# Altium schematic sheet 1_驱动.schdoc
size 604 x 431 mm; Symbol: Sheet-Symbol_A2; Device: Sheet-Symbol_A2; Company: 嘉立创EDA; Version: V1.0; Page Size: A2; @Project Name: 辉光管时钟成品; @Page Count: 1; @Update Date: 2024-01-29; @Create Date: 2024-01-25; @Schematic Name: Schematic1; @Page No: 1; @Page Name: 驱动
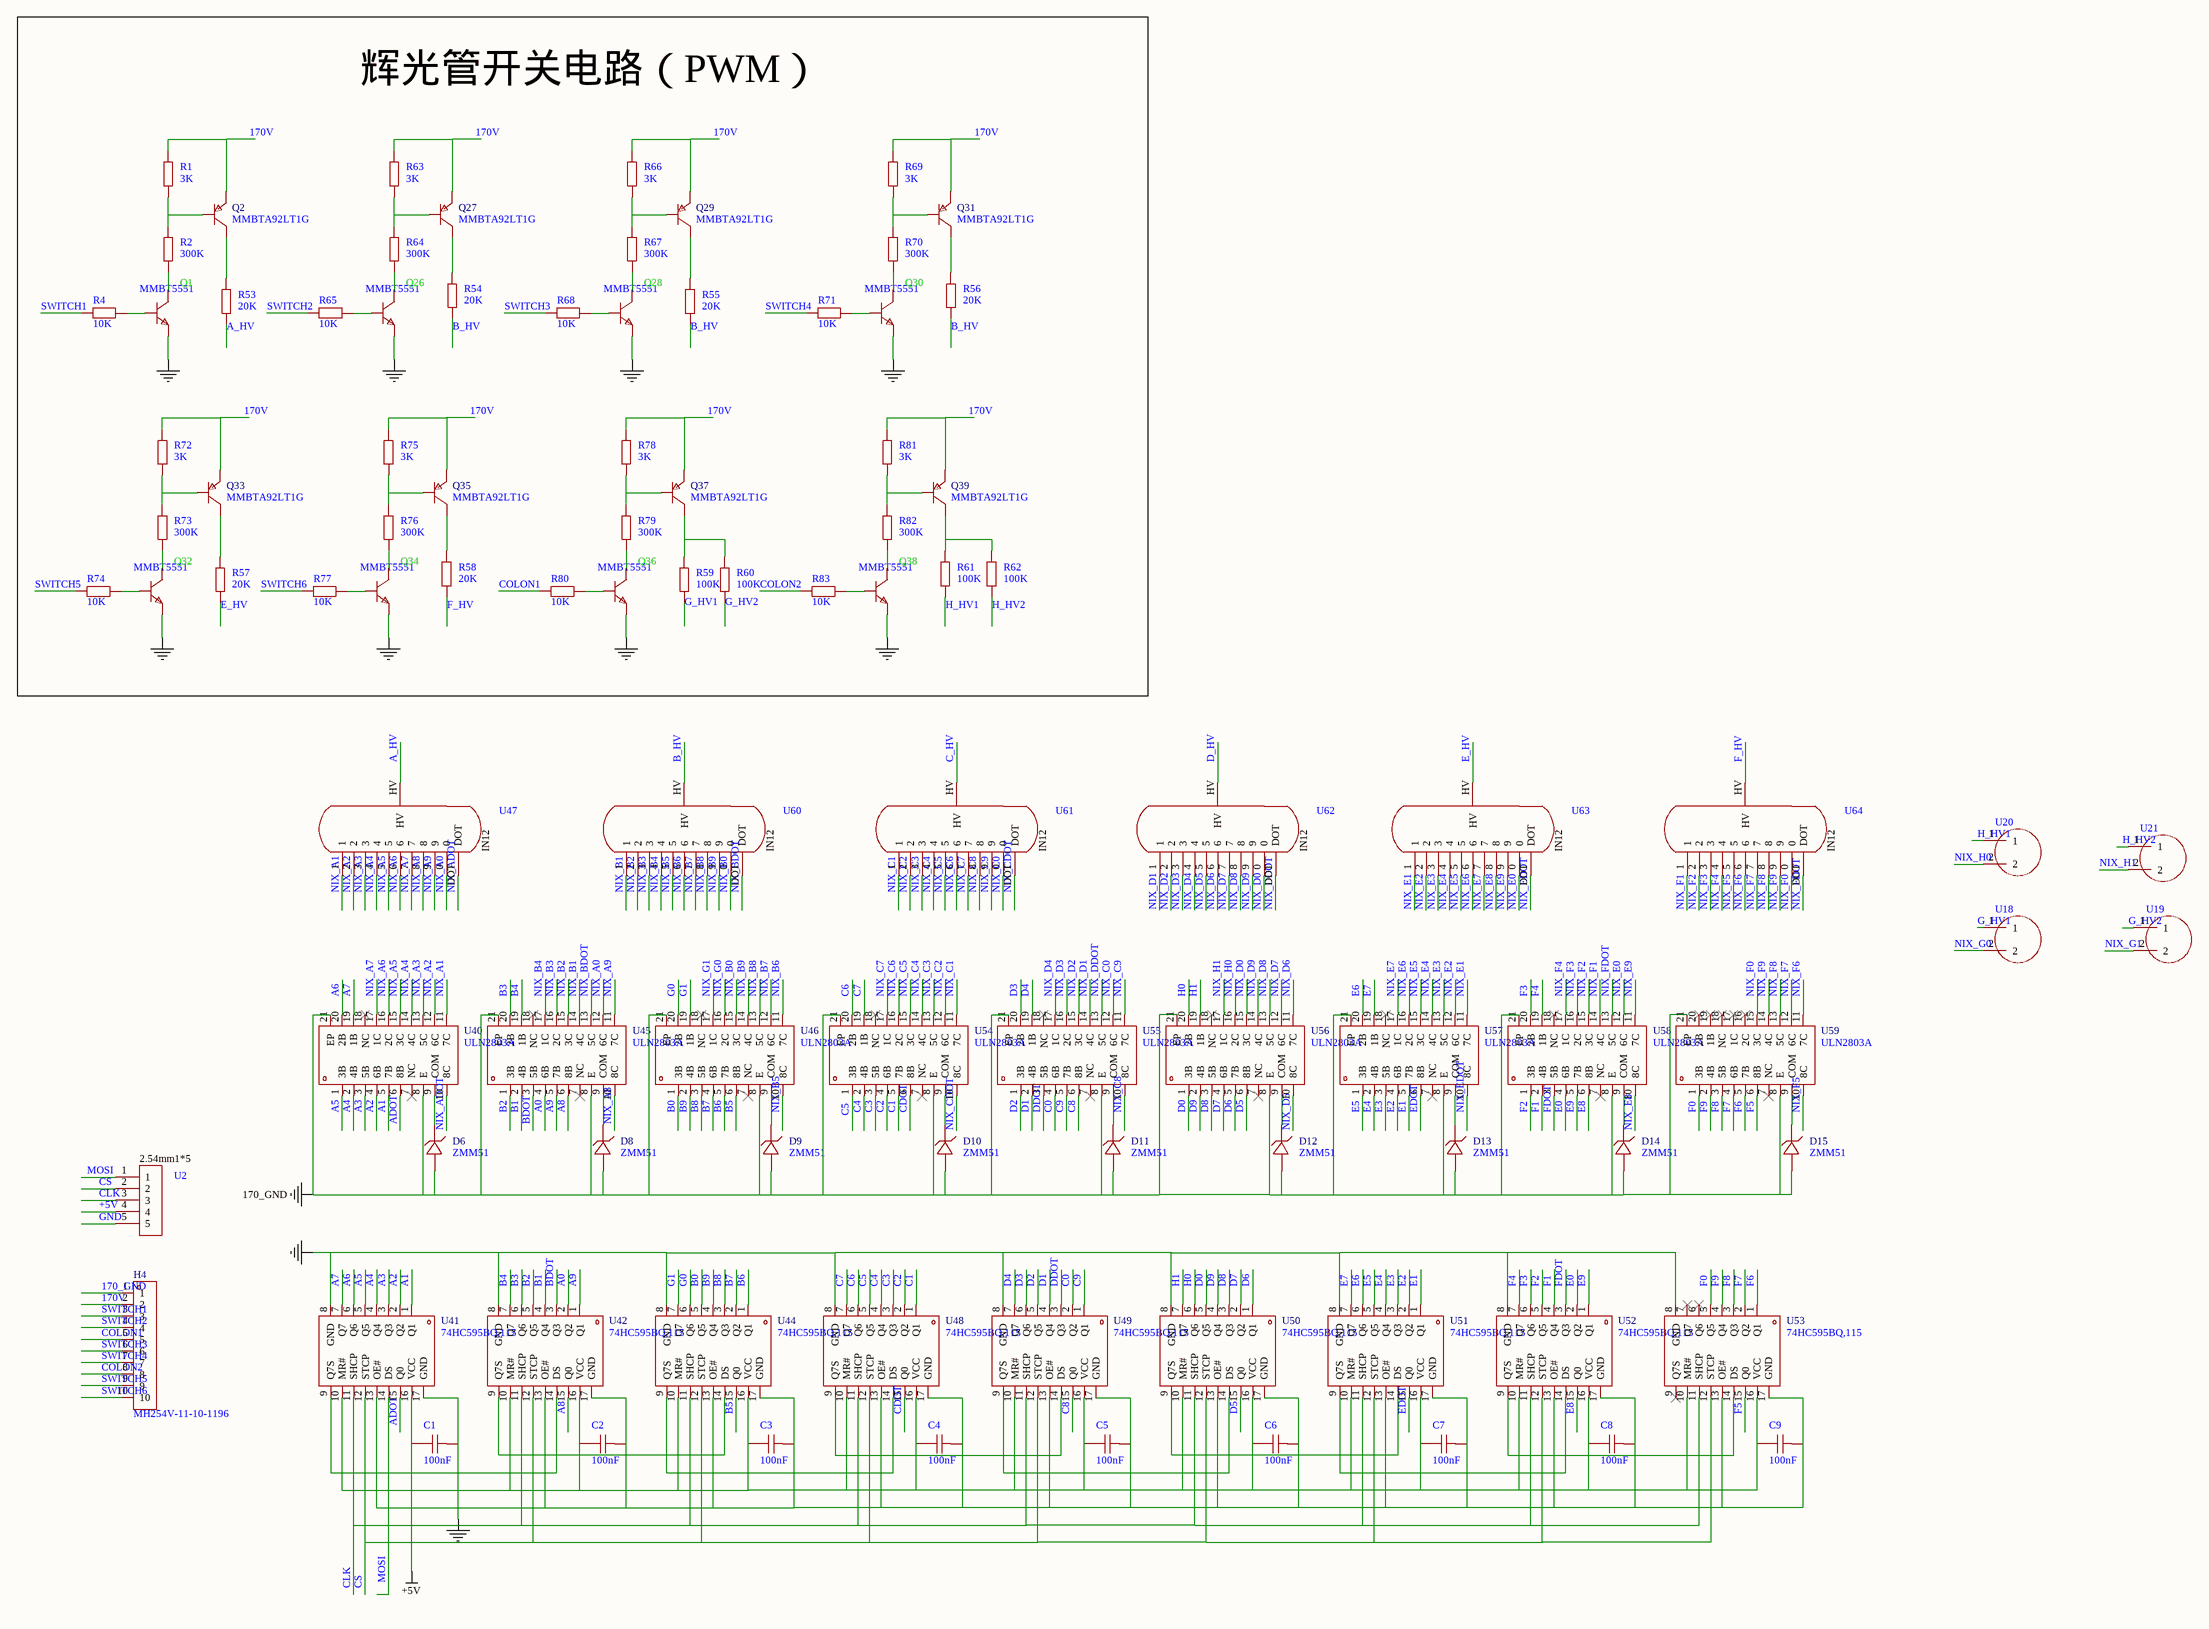
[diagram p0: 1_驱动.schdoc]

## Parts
C1  100nF  [C0603]
C2  100nF  [C0603]
C3  100nF  [C0603]
C4  100nF  [C0603]
C5  100nF  [C0603]
C6  100nF  [C0603]
C7  100nF  [C0603]
C8  100nF  [C0603]
C9  100nF  [C0603]
D6  ZMM51  [LL-34_L3.5-W1.5-RD]
D8  ZMM51  [LL-34_L3.5-W1.5-RD]
D9  ZMM51  [LL-34_L3.5-W1.5-RD]
D10  ZMM51  [LL-34_L3.5-W1.5-RD]
D11  ZMM51  [LL-34_L3.5-W1.5-RD]
D12  ZMM51  [LL-34_L3.5-W1.5-RD]
D13  ZMM51  [LL-34_L3.5-W1.5-RD]
D14  ZMM51  [LL-34_L3.5-W1.5-RD]
D15  ZMM51  [LL-34_L3.5-W1.5-RD]
H4  MH254V-11-10-1196  [HDR-TH_10P-P2.54-V-M]
Q1  MMBT5551  [SOT-23-3_L2.9-W1.3-P1.90-LS2.4-BR]
Q2  MMBTA92LT1G  [SOT-23-3_L2.9-W1.6-P1.90-LS2.8-BR]
Q26  MMBT5551  [SOT-23-3_L2.9-W1.3-P1.90-LS2.4-BR]
Q27  MMBTA92LT1G  [SOT-23-3_L2.9-W1.6-P1.90-LS2.8-BR]
Q28  MMBT5551  [SOT-23-3_L2.9-W1.3-P1.90-LS2.4-BR]
Q29  MMBTA92LT1G  [SOT-23-3_L2.9-W1.6-P1.90-LS2.8-BR]
Q30  MMBT5551  [SOT-23-3_L2.9-W1.3-P1.90-LS2.4-BR]
Q31  MMBTA92LT1G  [SOT-23-3_L2.9-W1.6-P1.90-LS2.8-BR]
Q32  MMBT5551  [SOT-23-3_L2.9-W1.3-P1.90-LS2.4-BR]
Q33  MMBTA92LT1G  [SOT-23-3_L2.9-W1.6-P1.90-LS2.8-BR]
Q34  MMBT5551  [SOT-23-3_L2.9-W1.3-P1.90-LS2.4-BR]
Q35  MMBTA92LT1G  [SOT-23-3_L2.9-W1.6-P1.90-LS2.8-BR]
Q36  MMBT5551  [SOT-23-3_L2.9-W1.3-P1.90-LS2.4-BR]
Q37  MMBTA92LT1G  [SOT-23-3_L2.9-W1.6-P1.90-LS2.8-BR]
Q38  MMBT5551  [SOT-23-3_L2.9-W1.3-P1.90-LS2.4-BR]
Q39  MMBTA92LT1G  [SOT-23-3_L2.9-W1.6-P1.90-LS2.8-BR]
R1  3K  [R0603]
R2  300K  [R0603]
R4  10K  [R0603]
R53  20K  [R0603]
R54  20K  [R0603]
R55  20K  [R0603]
R56  20K  [R0603]
R57  20K  [R0603]
R58  20K  [R0603]
R59  100K  [R0603]
R60  100K  [R0603]
R61  100K  [R0603]
R62  100K  [R0603]
R63  3K  [R0603]
R64  300K  [R0603]
R65  10K  [R0603]
R66  3K  [R0603]
R67  300K  [R0603]
R68  10K  [R0603]
R69  3K  [R0603]
R70  300K  [R0603]
R71  10K  [R0603]
R72  3K  [R0603]
R73  300K  [R0603]
R74  10K  [R0603]
R75  3K  [R0603]
R76  300K  [R0603]
R77  10K  [R0603]
R78  3K  [R0603]
R79  300K  [R0603]
R80  10K  [R0603]
R81  3K  [R0603]
R82  300K  [R0603]
R83  10K  [R0603]
U2  (no value)  [2.54mm1*5]
U18  (no value)  [6*13氖泡]
U19  (no value)  [6*13氖泡]
U20  (no value)  [6*13氖泡]
U21  (no value)  [6*13氖泡]
U40  ULN2803A  [QFN-20_L4.0-W4.0-P0.50-BL-EP]
U41  74HC595BQ,115  [DHVQFN-16_L3.5-W2.5-P0.50-BL-EP]
U42  74HC595BQ,115  [DHVQFN-16_L3.5-W2.5-P0.50-BL-EP]
U44  74HC595BQ,115  [DHVQFN-16_L3.5-W2.5-P0.50-BL-EP]
U45  ULN2803A  [QFN-20_L4.0-W4.0-P0.50-BL-EP]
U46  ULN2803A  [QFN-20_L4.0-W4.0-P0.50-BL-EP]
U47  (no value)  [IN12]
U48  74HC595BQ,115  [DHVQFN-16_L3.5-W2.5-P0.50-BL-EP]
U49  74HC595BQ,115  [DHVQFN-16_L3.5-W2.5-P0.50-BL-EP]
U50  74HC595BQ,115  [DHVQFN-16_L3.5-W2.5-P0.50-BL-EP]
U51  74HC595BQ,115  [DHVQFN-16_L3.5-W2.5-P0.50-BL-EP]
U52  74HC595BQ,115  [DHVQFN-16_L3.5-W2.5-P0.50-BL-EP]
U53  74HC595BQ,115  [DHVQFN-16_L3.5-W2.5-P0.50-BL-EP]
U54  ULN2803A  [QFN-20_L4.0-W4.0-P0.50-BL-EP]
U55  ULN2803A  [QFN-20_L4.0-W4.0-P0.50-BL-EP]
U56  ULN2803A  [QFN-20_L4.0-W4.0-P0.50-BL-EP]
U57  ULN2803A  [QFN-20_L4.0-W4.0-P0.50-BL-EP]
U58  ULN2803A  [QFN-20_L4.0-W4.0-P0.50-BL-EP]
U59  ULN2803A  [QFN-20_L4.0-W4.0-P0.50-BL-EP]
U60  (no value)  [IN12]
U61  (no value)  [IN12]
U62  (no value)  [IN12]
U63  (no value)  [IN12]
U64  (no value)  [IN12]

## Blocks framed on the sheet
辉光管开关电路（PWM）: Q1 Q2 Q26-Q39 R1 R2 R4 R53-R83

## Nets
170_GND: D6.2(A) D8.2(A) D9.2(A) D10.2(A) D11.2(A) D12.2(A) D13.2(A) D14.2(A) D15.2(A) H4.1 U40.8(E) U40.21(EP) U45.8(E) U45.21(EP) U46.8(E) U46.21(EP) U54.8(E) U54.21(EP) U55.8(E) U55.21(EP) U56.8(E) U56.21(EP) U57.8(E) U57.21(EP) U58.8(E) U58.21(EP) U59.8(E) U59.21(EP)
+5V: C1.1 C2.1 C3.1 C4.1 C5.1 C6.1 C7.1 C8.1 C9.1 U2.4 U41.10(MR#) U41.16(VCC) U42.10(MR#) U42.16(VCC) U44.10(MR#) U44.16(VCC) U48.10(MR#) U48.16(VCC) U49.10(MR#) U49.16(VCC) U50.10(MR#) U50.16(VCC) U51.10(MR#) U51.16(VCC) U52.10(MR#) U52.16(VCC) U53.10(MR#) U53.16(VCC)
GND: C1.2 C2.2 C3.2 C4.2 C5.2 C6.2 C7.2 C8.2 C9.2 Q1.2(E) Q26.2(E) Q28.2(E) Q30.2(E) Q32.2(E) Q34.2(E) Q36.2(E) Q38.2(E) U2.5 U41.8(GND) U41.13(OE#) U41.17(GND) U42.8(GND) U42.13(OE#) U42.17(GND) U44.8(GND) U44.13(OE#) U44.17(GND) U48.8(GND) U48.13(OE#) U48.17(GND) U49.8(GND) U49.13(OE#) U49.17(GND) U50.8(GND) U50.13(OE#) U50.17(GND) U51.8(GND) U51.13(OE#) U51.17(GND) U52.8(GND) U52.13(OE#) U52.17(GND) U53.8(GND) U53.13(OE#) U53.17(GND)
170V: H4.2 Q2.2(E) Q27.2(E) Q29.2(E) Q31.2(E) Q33.2(E) Q35.2(E) Q37.2(E) Q39.2(E) R1.2 R63.2 R66.2 R69.2 R72.2 R75.2 R78.2 R81.2
A0: U42.2(Q2) U45.4(6B)
A1: U40.5(7B) U41.1(Q1)
A2: U40.4(6B) U41.2(Q2)
A3: U40.3(5B) U41.3(Q3)
A4: U40.2(4B) U41.4(Q4)
A5: U40.1(3B) U41.5(Q5)
A6: U40.20(2B) U41.6(Q6)
A7: U40.19(1B) U41.7(Q7)
A8: U42.15(Q0) U45.6(8B)
A9: U42.1(Q1) U45.5(7B)
A_HV: R53.1 U47.HV
ADOT: U40.6(8B) U41.15(Q0)
B0: U44.5(Q5) U46.1(3B)
B1: U42.4(Q4) U45.2(4B)
B2: U42.5(Q5) U45.1(3B)
B3: U42.6(Q6) U45.20(2B)
B4: U42.7(Q7) U45.19(1B)
B5: U44.15(Q0) U46.6(8B)
B6: U44.1(Q1) U46.5(7B)
B7: U44.2(Q2) U46.4(6B)
B8: U44.3(Q3) U46.3(5B)
B9: U44.4(Q4) U46.2(4B)
B_HV: R54.1 R55.1 R56.1 U60.HV
BDOT: U42.3(Q3) U45.3(5B)
C0: U49.2(Q2) U55.4(6B)
C1: U48.1(Q1) U54.5(7B)
C2: U48.2(Q2) U54.4(6B)
C3: U48.3(Q3) U54.3(5B)
C4: U48.4(Q4) U54.2(4B)
C5: U48.5(Q5) U54.1(3B)
C6: U48.6(Q6) U54.20(2B)
C7: U48.7(Q7) U54.19(1B)
C8: U49.15(Q0) U55.6(8B)
C9: U49.1(Q1) U55.5(7B)
C_HV: U61.HV
CDOT: U48.15(Q0) U54.6(8B)
CLK: U2.3 U41.11(SHCP) U42.11(SHCP) U44.11(SHCP) U48.11(SHCP) U49.11(SHCP) U50.11(SHCP) U51.11(SHCP) U52.11(SHCP) U53.11(SHCP)
COLON1: H4.5 R80.1
COLON2: H4.8 R83.1
CS: U2.2 U41.12(STCP) U42.12(STCP) U44.12(STCP) U48.12(STCP) U49.12(STCP) U50.12(STCP) U51.12(STCP) U52.12(STCP) U53.12(STCP)
D0: U50.5(Q5) U56.1(3B)
D1: U49.4(Q4) U55.2(4B)
D2: U49.5(Q5) U55.1(3B)
D3: U49.6(Q6) U55.20(2B)
D4: U49.7(Q7) U55.19(1B)
D5: U50.15(Q0) U56.6(8B)
D6: U50.1(Q1) U56.5(7B)
D7: U50.2(Q2) U56.4(6B)
D8: U50.3(Q3) U56.3(5B)
D9: U50.4(Q4) U56.2(4B)
D_HV: U62.HV
DDOT: U49.3(Q3) U55.3(5B)
E0: U52.2(Q2) U58.4(6B)
E1: U51.1(Q1) U57.5(7B)
E2: U51.2(Q2) U57.4(6B)
E3: U51.3(Q3) U57.3(5B)
E4: U51.4(Q4) U57.2(4B)
E5: U51.5(Q5) U57.1(3B)
E6: U51.6(Q6) U57.20(2B)
E7: U51.7(Q7) U57.19(1B)
E8: U52.15(Q0) U58.6(8B)
E9: U52.1(Q1) U58.5(7B)
E_HV: R57.1 U63.HV
EDOT: U51.15(Q0) U57.6(8B)
F0: U53.5(Q5) U59.1(3B)
F1: U52.4(Q4) U58.2(4B)
F2: U52.5(Q5) U58.1(3B)
F3: U52.6(Q6) U58.20(2B)
F4: U52.7(Q7) U58.19(1B)
F5: U53.15(Q0) U59.6(8B)
F6: U53.1(Q1) U59.5(7B)
F7: U53.2(Q2) U59.4(6B)
F8: U53.3(Q3) U59.3(5B)
F9: U53.4(Q4) U59.2(4B)
F_HV: R58.1 U64.HV
FDOT: U52.3(Q3) U58.3(5B)
G0: U44.6(Q6) U46.20(2B)
G1: U44.7(Q7) U46.19(1B)
G_HV1: R59.1 U18.1
G_HV2: R60.1 U19.1
H0: U50.6(Q6) U56.20(2B)
H1: U50.7(Q7) U56.19(1B)
H_HV1: R61.1 U20.1
H_HV2: R62.1 U21.1
MOSI: U2.1 U41.14(DS)
NIX_A0: U45.12(6C) U47.0
NIX_A1: U40.11(7C) U47.1
NIX_A2: U40.12(6C) U47.2
NIX_A3: U40.13(5C) U47.3
NIX_A4: U40.14(4C) U47.4
NIX_A5: U40.15(3C) U47.5
NIX_A6: U40.16(2C) U47.6
NIX_A7: U40.17(1C) U47.7
NIX_A8: U45.10(8C) U47.8
NIX_A9: U45.11(7C) U47.9
NIX_ADOT: U40.10(8C) U47.DOT
NIX_B0: U46.15(3C) U60.0
NIX_B1: U45.14(4C) U60.1
NIX_B2: U45.15(3C) U60.2
NIX_B3: U45.16(2C) U60.3
NIX_B4: U45.17(1C) U60.4
NIX_B5: U46.10(8C) U60.5
NIX_B6: U46.11(7C) U60.6
NIX_B7: U46.12(6C) U60.7
NIX_B8: U46.13(5C) U60.8
NIX_B9: U46.14(4C) U60.9
NIX_BDOT: U45.13(5C) U60.DOT
NIX_C0: U55.12(6C) U61.0
NIX_C1: U54.11(7C) U61.1
NIX_C2: U54.12(6C) U61.2
NIX_C3: U54.13(5C) U61.3
NIX_C4: U54.14(4C) U61.4
NIX_C5: U54.15(3C) U61.5
NIX_C6: U54.16(2C) U61.6
NIX_C7: U54.17(1C) U61.7
NIX_C8: U55.10(8C) U61.8
NIX_C9: U55.11(7C) U61.9
NIX_CDOT: U54.10(8C) U61.DOT
NIX_D0: U56.15(3C) U62.0
NIX_D1: U55.14(4C) U62.1
NIX_D2: U55.15(3C) U62.2
NIX_D3: U55.16(2C) U62.3
NIX_D4: U55.17(1C) U62.4
NIX_D5: U56.10(8C) U62.5
NIX_D6: U56.11(7C) U62.6
NIX_D7: U56.12(6C) U62.7
NIX_D8: U56.13(5C) U62.8
NIX_D9: U56.14(4C) U62.9
NIX_DDOT: U55.13(5C) U62.DOT
NIX_E0: U58.12(6C) U63.0
NIX_E1: U57.11(7C) U63.1
NIX_E2: U57.12(6C) U63.2
NIX_E3: U57.13(5C) U63.3
NIX_E4: U57.14(4C) U63.4
NIX_E5: U57.15(3C) U63.5
NIX_E6: U57.16(2C) U63.6
NIX_E7: U57.17(1C) U63.7
NIX_E8: U58.10(8C) U63.8
NIX_E9: U58.11(7C) U63.9
NIX_EDOT: U57.10(8C) U63.DOT
NIX_F0: U59.15(3C) U64.0
NIX_F1: U58.14(4C) U64.1
NIX_F2: U58.15(3C) U64.2
NIX_F3: U58.16(2C) U64.3
NIX_F4: U58.17(1C) U64.4
NIX_F5: U59.10(8C) U64.5
NIX_F6: U59.11(7C) U64.6
NIX_F7: U59.12(6C) U64.7
NIX_F8: U59.13(5C) U64.8
NIX_F9: U59.14(4C) U64.9
NIX_FDOT: U58.13(5C) U64.DOT
NIX_G0: U18.2 U46.16(2C)
NIX_G1: U19.2 U46.17(1C)
NIX_H0: U20.2 U56.16(2C)
NIX_H1: U21.2 U56.17(1C)
SWITCH1: H4.3 R4.1
SWITCH2: H4.4 R65.1
SWITCH3: H4.6 R68.1
SWITCH4: H4.7 R71.1
SWITCH5: H4.9 R74.1
SWITCH6: H4.10 R77.1
NetD6_1: D6.1(C) U40.9(COM)
NetD8_1: D8.1(C) U45.9(COM)
NetD9_1: D9.1(C) U46.9(COM)
NetD10_1: D10.1(C) U54.9(COM)
NetD11_1: D11.1(C) U55.9(COM)
NetD12_1: D12.1(C) U56.9(COM)
NetD13_1: D13.1(C) U57.9(COM)
NetD14_1: D14.1(C) U58.9(COM)
NetD15_1: D15.1(C) U59.9(COM)
NetQ1_1: Q1.1(B) R4.2
NetQ1_3: Q1.3(C) R2.1
NetQ2_1: Q2.1(B) R1.1 R2.2
NetQ2_3: Q2.3(C) R53.2
NetQ26_1: Q26.1(B) R65.2
NetQ26_3: Q26.3(C) R64.1
NetQ27_1: Q27.1(B) R63.1 R64.2
NetQ27_3: Q27.3(C) R54.2
NetQ28_1: Q28.1(B) R68.2
NetQ28_3: Q28.3(C) R67.1
NetQ29_1: Q29.1(B) R66.1 R67.2
NetQ29_3: Q29.3(C) R55.2
NetQ30_1: Q30.1(B) R71.2
NetQ30_3: Q30.3(C) R70.1
NetQ31_1: Q31.1(B) R69.1 R70.2
NetQ31_3: Q31.3(C) R56.2
NetQ32_1: Q32.1(B) R74.2
NetQ32_3: Q32.3(C) R73.1
NetQ33_1: Q33.1(B) R72.1 R73.2
NetQ33_3: Q33.3(C) R57.2
NetQ34_1: Q34.1(B) R77.2
NetQ34_3: Q34.3(C) R76.1
NetQ35_1: Q35.1(B) R75.1 R76.2
NetQ35_3: Q35.3(C) R58.2
NetQ36_1: Q36.1(B) R80.2
NetQ36_3: Q36.3(C) R79.1
NetQ37_1: Q37.1(B) R78.1 R79.2
NetQ37_3: Q37.3(C) R59.2 R60.2
NetQ38_1: Q38.1(B) R83.2
NetQ38_3: Q38.3(C) R82.1
NetQ39_1: Q39.1(B) R81.1 R82.2
NetQ39_3: Q39.3(C) R61.2 R62.2
NetU41_9: U41.9(Q7S) U42.14(DS)
NetU42_9: U42.9(Q7S) U44.14(DS)
NetU44_9: U44.9(Q7S) U48.14(DS)
NetU48_9: U48.9(Q7S) U49.14(DS)
NetU49_9: U49.9(Q7S) U50.14(DS)
NetU50_9: U50.9(Q7S) U51.14(DS)
NetU51_9: U51.9(Q7S) U52.14(DS)
NetU52_9: U52.9(Q7S) U53.14(DS)

Not connected (* = marked no-connect by the designer): U40 7(NC)* 18(NC)*; U45 7(NC)* 18(NC)*; U46 7(NC)* 18(NC)*; U53 6(Q6)* 7(Q7)* 9(Q7S)*; U54 7(NC)* 18(NC)*; U55 7(NC)* 18(NC)*; U56 7(NC)* 18(NC)*; U57 7(NC)* 18(NC)*; U58 7(NC)* 18(NC)*; U59 7(NC)* 16(2C)* 17(1C)* 18(NC)* 19(1B)* 20(2B)*

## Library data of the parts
C1-C9 = CAP_0603: Symbol: CapAcitance; Convert to PCB: yes
D6 D8-D15 = ZMM51: Manufacturer: ST(先科); Add into BOM: yes; Diode Configuration: 独立式; Zener Voltage (Nom): 51V; Reverse Leakage Current (Ir): 100nA@39V; Zener Voltage (Range): 48V~54V; Power Dissipation: 500mW; Zener Impedance (Zzt): 125Ω
H4 = MH254V-11-10-1196: Manufacturer: XFCN(兴飞); Add into BOM: yes
Q1 Q26 Q28 Q30 Q32 Q34 Q36 Q38 = MMBT5551_C2145: Manufacturer: CJ(江苏长电/长晶); Add into BOM: yes; Transistor Type: NPN; Collector-Emitter Breakdown Voltage (Vceo): 160V; Collector Current (Ic): 600mA; Power Dissipation (Pd): 300mW; Collector Cut-Off Current (Icbo): 50nA; Collector-Emitter Saturation Voltage (VCE(sat)@Ic,Ib): 200mV@50mA,5mA; DC Current Gain (hFE@Ic,Vce): 200@10mA,5V; Transition Frequency (fT): 100MHz; Pin Type: Undefined
Q2 Q27 Q29 Q31 Q33 Q35 Q37 Q39 = MMBTA92LT1G: Manufacturer: onsemi(安森美); Add into BOM: yes; DC Current Gain (hFE@Ic,Vce): 25@30mA,10V; Power Dissipation (Pd): 300mW; Transition Frequency (fT): 50MHz; Collector-Emitter Breakdown Voltage (Vceo): 300V; Collector Current (Ic): 500mA; Collector Cut-Off Current (Icbo): 250nA; Collector-Emitter Saturation Voltage (VCE(sat)@Ic,Ib): 500mV@20mA,2mA; Transistor Type: PNP
R1 R2 R4 R53-R83 = Res_0603: Symbol: 电阻; Convert to PCB: yes
U2 = 2.54mm1*5: Add into BOM: yes
U18-U21 = 氖泡: Add into BOM: yes
U40 U45 U46 U54-U59 = ULN2803A_C493377: Manufacturer: Mixic(中科芯亿达); Add into BOM: yes
U41 U42 U44 U48-U53 = 74HC595BQ,115: Manufacturer: Nexperia(安世); Add into BOM: yes
U47 U60-U64 = IN12: Add into BOM: yes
